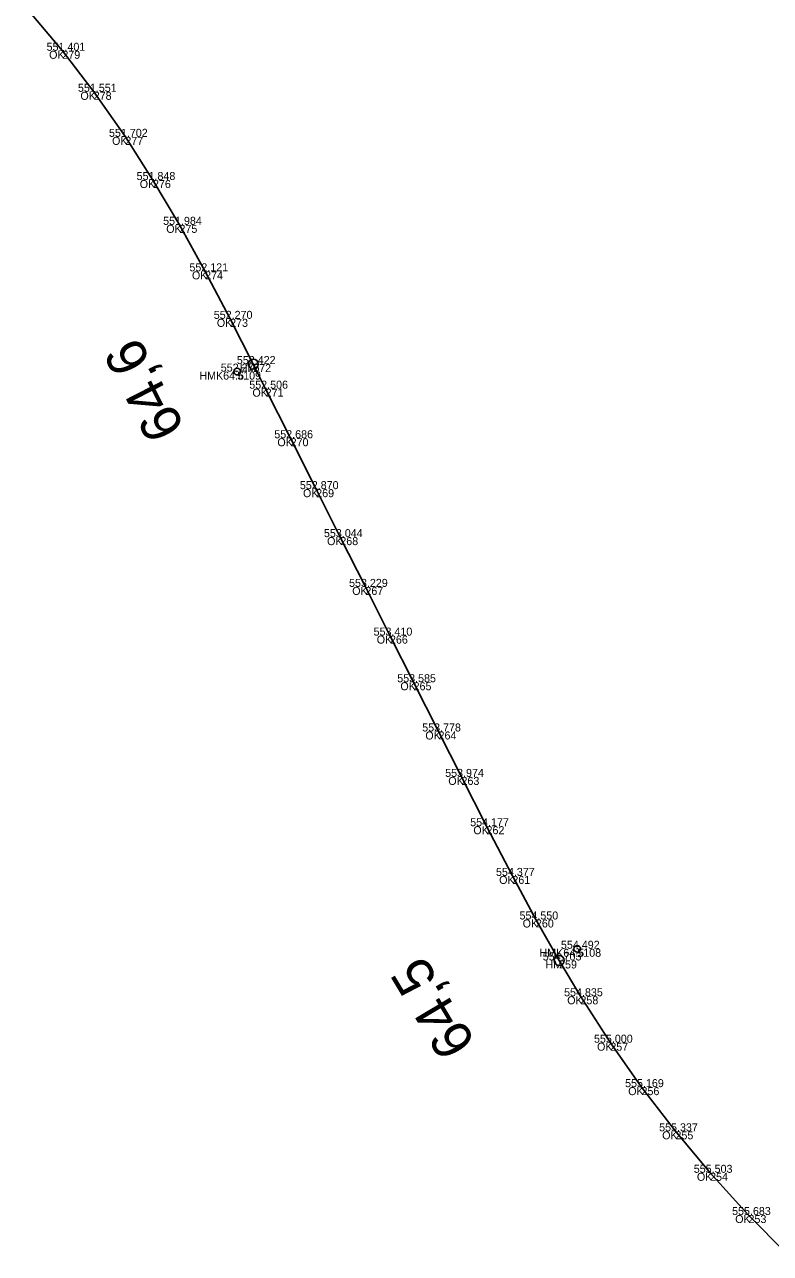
# Model space of a CAD drawing. Extents: x -621782 to -610392, y -1141853 to -1122321.
# Drawn here: x -620870.6 to -620758.8, y -1123103.7 to -1122919.5 of the extents above; entities that cross this region are included whole.
import ezdxf

# ---------------------------------------------------------------- set-up
doc = ezdxf.new("R2010")
doc.units = 0
for name, color, linetype in [('Vrstva 1', 7, 'Continuous'), ('Vrstva 60', 7, 'Continuous'), ('Vrstva 61', 7, 'Continuous'), ('Vrstva 62', 7, 'Continuous'), ('Vrstva 7', 7, 'Continuous')]:
    doc.layers.add(name, color=color, linetype=linetype)

msp = doc.modelspace()

# ---------------------------------------------------------------- linework, layer by layer
at = {"layer": 'Vrstva 1'}
msp.add_lwpolyline([(-620756.43, -1123103.66), (-620762.11, -1123097.91), (-620767.86, -1123091.58), (-620773.05, -1123085.36), (-620778.14, -1123078.74), (-620782.81, -1123072.08), (-620787.29, -1123065.12), (-620790.49, -1123059.75), (-620793.96, -1123053.61), (-620797.49, -1123047.08), (-620801.36, -1123039.63), (-620805.11, -1123032.24), (-620808.55, -1123025.43), (-620812.29, -1123018.05), (-620815.83, -1123011.06), (-620819.51, -1123003.76), (-620823.27, -1122996.3), (-620826.88, -1122989.11), (-620830.71, -1122981.48), (-620834.46, -1122974.05), (-620836.32, -1122970.36), (-620839.78, -1122963.58), (-620843.52, -1122956.46), (-620847.37, -1122949.49), (-620851.34, -1122942.77), (-620855.48, -1122936.3), (-620860.22, -1122929.55), (-620864.92, -1122923.4), (-620870.58, -1122916.66)], dxfattribs=at)
at = {"layer": 'Vrstva 60'}
for p, q in [((-620864.92, -1122923.4), (-620864.92, -1122923.4)), ((-620860.22, -1122929.55), (-620860.22, -1122929.55)), ((-620855.48, -1122936.3), (-620855.48, -1122936.3)), ((-620851.34, -1122942.77), (-620851.34, -1122942.77)), ((-620847.37, -1122949.49), (-620847.37, -1122949.49)), ((-620843.52, -1122956.46), (-620843.52, -1122956.46)), ((-620839.78, -1122963.58), (-620839.78, -1122963.58)), ((-620838.72, -1122971.49), (-620838.72, -1122971.49)), ((-620836.32, -1122970.36), (-620836.32, -1122970.36)), ((-620834.46, -1122974.05), (-620834.46, -1122974.05)), ((-620830.71, -1122981.48), (-620830.71, -1122981.48)), ((-620826.88, -1122989.11), (-620826.88, -1122989.11)), ((-620823.27, -1122996.3), (-620823.27, -1122996.3)), ((-620819.51, -1123003.76), (-620819.51, -1123003.76)), ((-620815.83, -1123011.06), (-620815.83, -1123011.06)), ((-620812.29, -1123018.05), (-620812.29, -1123018.05)), ((-620808.55, -1123025.43), (-620808.55, -1123025.43)), ((-620805.11, -1123032.24), (-620805.11, -1123032.24)), ((-620801.36, -1123039.63), (-620801.36, -1123039.63)), ((-620797.49, -1123047.08), (-620797.49, -1123047.08)), ((-620793.96, -1123053.61), (-620793.96, -1123053.61)), ((-620787.76, -1123058), (-620787.76, -1123058)), ((-620790.49, -1123059.75), (-620790.49, -1123059.75)), ((-620787.29, -1123065.12), (-620787.29, -1123065.12)), ((-620782.81, -1123072.08), (-620782.81, -1123072.08)), ((-620778.14, -1123078.74), (-620778.14, -1123078.74)), ((-620773.05, -1123085.36), (-620773.05, -1123085.36)), ((-620767.86, -1123091.58), (-620767.86, -1123091.58)), ((-620762.11, -1123097.91), (-620762.11, -1123097.91))]:
    msp.add_line(p, q, dxfattribs=at)
at = {"layer": 'Vrstva 7'}
for p, q in [((-620838.7, -1122971.53), (-620838.75, -1122971.45)), ((-620787.73, -1123058.04), (-620787.78, -1123057.96))]:
    msp.add_line(p, q, dxfattribs=at)
for centre, radius in [((-620836.32, -1122970.36), 0.75), ((-620838.72, -1122971.49), 0.5), ((-620787.76, -1123058), 0.5), ((-620790.49, -1123059.75), 0.75)]:
    msp.add_circle(centre, radius, dxfattribs=at)

# ---------------------------------------------------------------- texts
at = {"layer": 'Vrstva 60'}
for s, p in [('279', (-620864.92, -1122924.6)), ('278', (-620860.22, -1122930.75)), ('277', (-620855.48, -1122937.5)), ('276', (-620851.34, -1122943.97)), ('275', (-620847.37, -1122950.69)), ('274', (-620843.52, -1122957.66)), ('273', (-620839.78, -1122964.78)), ('5109', (-620838.72, -1122972.69)), ('272', (-620836.32, -1122971.56)), ('271', (-620834.46, -1122975.25)), ('270', (-620830.71, -1122982.68)), ('269', (-620826.88, -1122990.31)), ('268', (-620823.27, -1122997.5)), ('267', (-620819.51, -1123004.96)), ('266', (-620815.83, -1123012.26)), ('265', (-620812.29, -1123019.25)), ('264', (-620808.55, -1123026.63)), ('263', (-620805.11, -1123033.44)), ('262', (-620801.36, -1123040.83)), ('261', (-620797.49, -1123048.28)), ('260', (-620793.96, -1123054.81)), ('5108', (-620787.76, -1123059.2)), ('259', (-620790.49, -1123060.95)), ('258', (-620787.29, -1123066.32)), ('257', (-620782.81, -1123073.28)), ('256', (-620778.14, -1123079.94)), ('255', (-620773.05, -1123086.56)), ('254', (-620767.86, -1123092.78)), ('253', (-620762.11, -1123099.11))]:
    msp.add_text(s, height=1.2, dxfattribs=at).set_placement(p)
at = {"layer": 'Vrstva 61'}
for s, p in [('551.401', (-620867.28, -1122923.4)), ('551.551', (-620862.58, -1122929.55)), ('551.702', (-620857.93, -1122936.3)), ('551.848', (-620853.79, -1122942.77)), ('551.984', (-620849.82, -1122949.49)), ('552.121', (-620845.88, -1122956.46)), ('552.270', (-620842.23, -1122963.58)), ('552.422', (-620838.77, -1122970.36)), ('552.276', (-620841.18, -1122971.49)), ('552.506', (-620836.91, -1122974.05)), ('552.686', (-620833.16, -1122981.48)), ('552.870', (-620829.33, -1122989.11)), ('553.044', (-620825.72, -1122996.3)), ('553.229', (-620821.96, -1123003.76)), ('553.410', (-620818.28, -1123011.06)), ('553.585', (-620814.74, -1123018.05)), ('553.778', (-620811, -1123025.43)), ('553.974', (-620807.56, -1123032.24)), ('554.177', (-620803.81, -1123039.63)), ('554.377', (-620799.94, -1123047.08)), ('554.550', (-620796.42, -1123053.61)), ('554.492', (-620790.21, -1123058)), ('554.703', (-620792.94, -1123059.75)), ('554.835', (-620789.74, -1123065.12)), ('555.000', (-620785.26, -1123072.08)), ('555.169', (-620780.6, -1123078.74)), ('555.337', (-620775.5, -1123085.36)), ('555.503', (-620770.31, -1123091.58)), ('555.683', (-620764.57, -1123097.91))]:
    msp.add_text(s, height=1.2, dxfattribs=at).set_placement(p)
at = {"layer": 'Vrstva 62'}
for s, p in [('OK', (-620866.9, -1122924.6)), ('OK', (-620862.21, -1122930.75)), ('OK', (-620857.47, -1122937.5)), ('OK', (-620853.32, -1122943.97)), ('OK', (-620849.35, -1122950.69)), ('OK', (-620845.5, -1122957.66)), ('OK', (-620841.77, -1122964.78)), ('HMK64.6', (-620844.39, -1122972.69)), ('HM', (-620838.35, -1122971.56)), ('OK', (-620836.44, -1122975.25)), ('OK', (-620832.7, -1122982.68)), ('OK', (-620828.86, -1122990.31)), ('OK', (-620825.25, -1122997.5)), ('OK', (-620821.49, -1123004.96)), ('OK', (-620817.81, -1123012.26)), ('OK', (-620814.27, -1123019.25)), ('OK', (-620810.53, -1123026.63)), ('OK', (-620807.09, -1123033.44)), ('OK', (-620803.34, -1123040.83)), ('OK', (-620799.47, -1123048.28)), ('OK', (-620795.95, -1123054.81)), ('HMK64.5', (-620793.43, -1123059.2)), ('HM', (-620792.52, -1123060.95)), ('OK', (-620789.27, -1123066.32)), ('OK', (-620784.8, -1123073.28)), ('OK', (-620780.13, -1123079.94)), ('OK', (-620775.04, -1123086.56)), ('OK', (-620769.84, -1123092.78)), ('OK', (-620764.1, -1123099.11))]:
    msp.add_text(s, height=1.2, dxfattribs=at).set_placement(p)
at = {"layer": 'Vrstva 7'}
for s, rotation, p in [('64,6', 117.0701, (-620846.45, -1122979.96)), ('64,5', 120.8114, (-620802.84, -1123072.14))]:
    msp.add_text(s, height=6, rotation=rotation, dxfattribs=at).set_placement(p)

doc.saveas('drawing.dxf')
